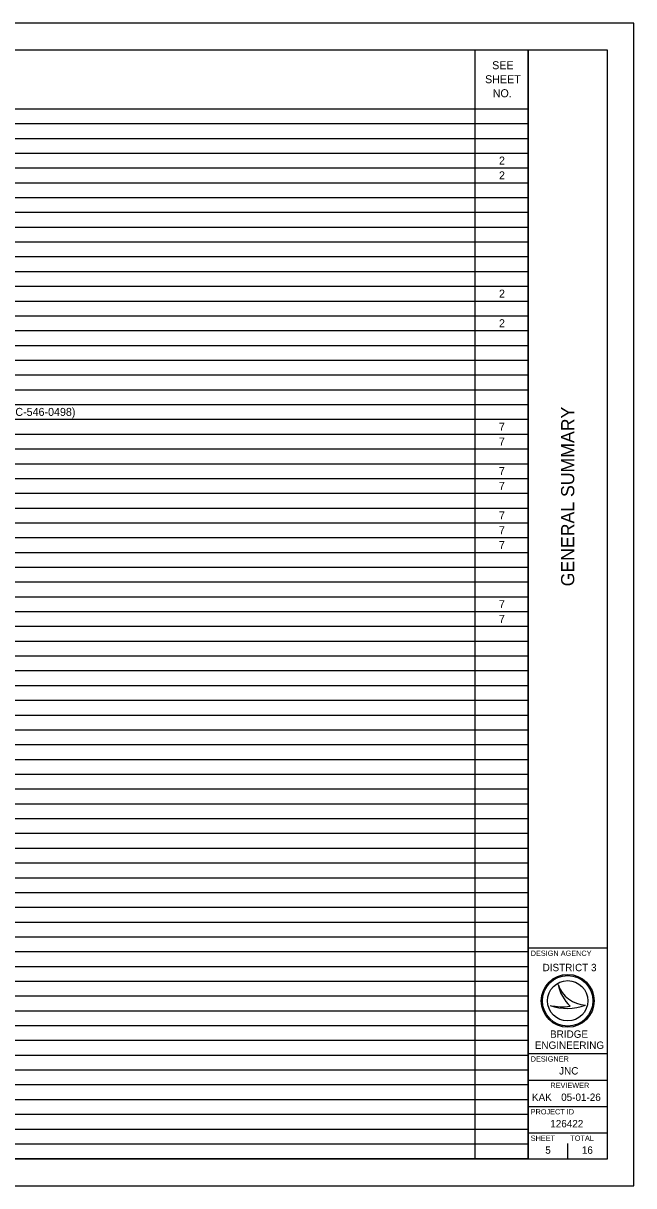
# Model space of a CAD drawing. Extents: x 0 to 34, y 0 to 22.
# Drawn here: x 22.45 to 34, y 0 to 22 of the extents above; entities that cross this region are included whole.
import ezdxf

# ---------------------------------------------------------------- set-up
doc = ezdxf.new("R2010")
doc.units = 0
for name, color, linetype in [('SH_Border', 7, 'Continuous'), ('SH_Cut_Line', 7, 'Continuous'), ('SH_Data', 7, 'Continuous'), ('SH_Text', 7, 'Continuous')]:
    doc.layers.add(name, color=color, linetype=linetype)

msp = doc.modelspace()

# ---------------------------------------------------------------- linework, layer by layer
at = {"layer": 'SH_Border'}
for p, q in [((32, 0.5), (32, 21.5)), ((32, 4.5), (33.5, 4.5)), ((32, 2.5), (33.5, 2.5)), ((32, 2), (33.5, 2)), ((32, 1.5), (33.5, 1.5)), ((32, 1), (33.5, 1))]:
    msp.add_line(p, q, dxfattribs=at)
msp.add_lwpolyline([(1.5, 21.5), (33.5, 21.5), (33.5, 0.5), (1.5, 0.5)], close=True, dxfattribs=at)
at = {"layer": 'SH_Cut_Line'}
msp.add_lwpolyline([(0, 0), (34, 0), (34, 22), (0, 22)], close=True, dxfattribs=at)
at = {"layer": 'SH_Data'}
for p, q in [((32.567, 3.81), (32.567, 3.81)), ((32.417, 3.41), (32.417, 3.41)), ((32.75, 3.5), (32.75, 3.5)), ((33.087, 3.419), (33.087, 3.419)), ((32.375, 0.675), (32.375, 0.675)), ((32.75, 0.5), (32.75, 0.8))]:
    msp.add_line(p, q, dxfattribs=at)
for radius in [0.5, 0.477, 0.477, 0.382]:
    msp.add_circle((32.75, 3.5), radius, dxfattribs=at)
for centre, radius, start, end in [((33.116, 3.998), 0.58, 198.9257, 198.9319), ((33.347, 3.97), 0.796, 191.6379, 191.6421), ((33.116, 3.998), 0.58, 198.9319, 267.1657), ((33.347, 3.97), 0.796, 191.6421, 226.0947), ((32.739, 4.37), 1.013, 251.4576, 290.0832), ((32.648, 4.654), 1.266, 259.4964, 259.4995), ((32.739, 4.37), 1.013, 251.4527, 251.4576), ((32.648, 4.654), 1.266, 259.4995, 276.6672)]:
    msp.add_arc(centre, radius, start, end, dxfattribs=at)
at = {"layer": 'SH_Text'}
for p, q in [((1.5, 21.5), (32, 21.5)), ((30.996, 21.5), (30.996, 0.514)), ((32, 21.5), (32, 0.514)), ((1.5, 20.381), (32, 20.381)), ((1.5, 20.101), (32, 20.101)), ((1.5, 19.821), (32, 19.821)), ((1.5, 19.541), (32, 19.541)), ((1.5, 19.261), (32, 19.261)), ((1.5, 18.982), (32, 18.982)), ((1.5, 18.702), (32, 18.702)), ((1.5, 18.422), (32, 18.422)), ((1.5, 18.142), (32, 18.142)), ((1.5, 17.862), (32, 17.862)), ((1.5, 17.583), (32, 17.583)), ((1.5, 17.303), (32, 17.303)), ((1.5, 17.023), (32, 17.023)), ((1.5, 16.743), (32, 16.743)), ((1.5, 16.463), (32, 16.463)), ((1.5, 16.183), (32, 16.183)), ((1.5, 15.904), (32, 15.904)), ((1.5, 15.624), (32, 15.624)), ((1.5, 15.344), (32, 15.344)), ((1.5, 15.064), (32, 15.064)), ((1.5, 14.784), (32, 14.784)), ((1.5, 14.505), (32, 14.505)), ((1.5, 14.225), (32, 14.225)), ((1.5, 13.945), (32, 13.945)), ((1.5, 13.665), (32, 13.665)), ((1.5, 13.385), (32, 13.385)), ((1.5, 13.106), (32, 13.106)), ((1.5, 12.826), (32, 12.826)), ((1.5, 12.546), (32, 12.546)), ((1.5, 12.266), (32, 12.266)), ((1.5, 11.986), (32, 11.986)), ((1.5, 11.706), (32, 11.706)), ((1.5, 11.427), (32, 11.427)), ((1.5, 11.147), (32, 11.147)), ((1.5, 10.867), (32, 10.867)), ((1.5, 10.587), (32, 10.587)), ((1.5, 10.307), (32, 10.307)), ((1.5, 10.028), (32, 10.028)), ((1.5, 9.748), (32, 9.748)), ((1.5, 9.468), (32, 9.468)), ((1.5, 9.188), (32, 9.188)), ((1.5, 8.908), (32, 8.908)), ((1.5, 8.628), (32, 8.628)), ((1.5, 8.349), (32, 8.349)), ((1.5, 8.069), (32, 8.069)), ((1.5, 7.789), (32, 7.789)), ((1.5, 7.509), (32, 7.509)), ((1.5, 7.229), (32, 7.229)), ((1.5, 6.95), (32, 6.95)), ((1.5, 6.67), (32, 6.67)), ((1.5, 6.39), (32, 6.39)), ((1.5, 6.11), (32, 6.11)), ((1.5, 5.83), (32, 5.83)), ((1.5, 5.55), (32, 5.55)), ((1.5, 5.271), (32, 5.271)), ((1.5, 4.991), (32, 4.991)), ((1.5, 4.711), (32, 4.711)), ((1.5, 4.431), (32, 4.431)), ((1.5, 4.151), (32, 4.151)), ((1.5, 3.872), (32, 3.872)), ((1.5, 3.592), (32, 3.592)), ((1.5, 3.312), (32, 3.312)), ((1.5, 3.032), (32, 3.032)), ((1.5, 2.752), (32, 2.752)), ((1.5, 2.472), (32, 2.472)), ((1.5, 2.193), (32, 2.193)), ((1.5, 1.913), (32, 1.913)), ((1.5, 1.633), (32, 1.633)), ((1.5, 1.353), (32, 1.353)), ((1.5, 1.073), (32, 1.073)), ((1.5, 0.794), (32, 0.794)), ((1.5, 0.514), (32, 0.514))]:
    msp.add_line(p, q, dxfattribs=at)

# ---------------------------------------------------------------- texts
at = {"layer": 'SH_Data'}
msp.add_text('GENERAL SUMMARY', height=0.25, rotation=90, dxfattribs=at).set_placement((32.875, 11.344))
for s, height, p in [('DESIGN AGENCY', 0.1, (32.05, 4.35)), ('DESIGNER', 0.1, (32.05, 2.35)), ('JNC', 0.14, (32.588, 2.105)), ('REVIEWER', 0.1, (32.422, 1.85)), ('KAK', 0.14, (32.074, 1.605)), ('05-01-26', 0.14, (32.627, 1.605)), ('PROJECT ID', 0.1, (32.05, 1.35)), ('126422', 0.14, (32.421, 1.105)), ('SHEET', 0.1, (32.05, 0.85)), ('TOTAL', 0.1, (32.8, 0.85)), ('5', 0.14, (32.326, 0.605)), ('16', 0.14, (33.018, 0.605))]:
    msp.add_text(s, height=height, dxfattribs=at).set_placement(p)
at = {"layer": 'SH_Text'}
for s, height, p in [('SEE ', 0.1514, (31.321, 21.13)), ('SHEET ', 0.1514, (31.187, 20.865)), ('NO.', 0.1514, (31.332, 20.6)), ('2', 0.151, (31.45, 19.326)), ('2', 0.151, (31.45, 19.046)), ('2', 0.151, (31.45, 16.807)), ('2', 0.151, (31.45, 16.248)), ('STRUCTURE OVER 20 FOOT SPAN (RIC-546-0498)', 0.15143, (18.586, 14.569)), ('7', 0.151, (31.449, 14.289)), ('7', 0.151, (31.449, 14.009)), ('7', 0.151, (31.449, 13.45)), ('7', 0.151, (31.449, 13.17)), ('7', 0.151, (31.449, 12.61)), ('7', 0.151, (31.449, 12.33)), ('7', 0.151, (31.449, 12.05)), ('7', 0.151, (31.449, 10.931)), ('7', 0.151, (31.449, 10.651)), ('DISTRICT 3', 0.14, (32.276, 4.06)), ('BRIDGE', 0.14, (32.417, 2.8)), ('ENGINEERING', 0.14, (32.128, 2.59))]:
    msp.add_text(s, height=height, dxfattribs=at).set_placement(p)

doc.saveas('drawing.dxf')
